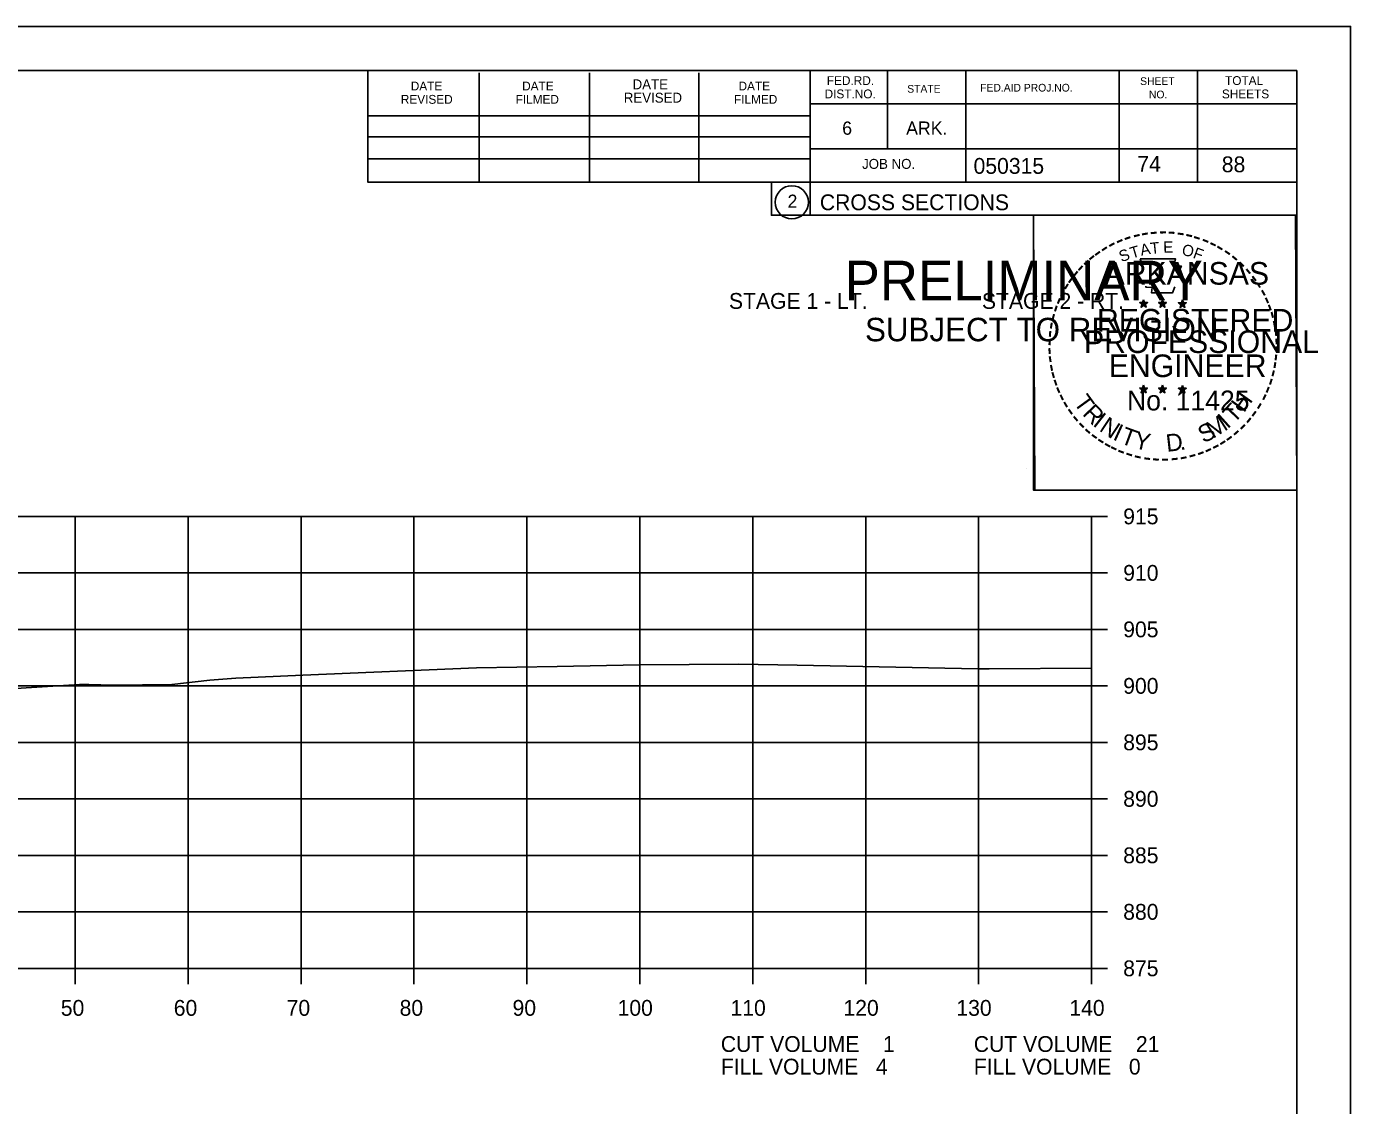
# Model space of a CAD drawing. Extents: x 1486524 to 1499135, y 326561 to 337924.
# Drawn here: x 1489028.6 to 1489145.8, y 333323.8 to 333419.3 of the extents above; entities that cross this region are included whole.
import ezdxf

# ---------------------------------------------------------------- set-up
doc = ezdxf.new("R2010")
doc.units = 0
for name, color, linetype in [('Default', 7, 'Continuous'), ('E_Const Align', 7, 'Continuous'), ('E_Const Align Station', 7, 'Continuous'), ('E_Ownership Information', 7, 'Continuous'), ('E_Property Line', 7, 'Continuous'), ('E_Quarter Calls', 7, 'Continuous'), ('E_Section Line', 7, 'Continuous'), ('E_Station Offset', 7, 'Continuous'), ('E_Tract Number', 7, 'Continuous'), ('S_SIXTEEN_SECTION', 7, 'Continuous')]:
    doc.layers.add(name, color=color, linetype=linetype)

msp = doc.modelspace()

# ---------------------------------------------------------------- linework, layer by layer
at = {"layer": 'E_Const Align'}
for p, q in [((1489122.89, 333335.96), (1489122.89, 333375.96)), ((1489124.29, 333375.96), (1489122.89, 333375.96)), ((1489124.29, 333370.96), (1489122.89, 333370.96)), ((1489124.29, 333365.96), (1489122.89, 333365.96)), ((1489124.29, 333360.96), (1489122.89, 333360.96)), ((1489124.29, 333355.96), (1489122.89, 333355.96)), ((1489124.29, 333350.96), (1489122.89, 333350.96)), ((1489124.29, 333345.96), (1489122.89, 333345.96)), ((1489124.29, 333340.96), (1489122.89, 333340.96)), ((1488842.89, 333335.96), (1489122.89, 333335.96)), ((1489032.89, 333334.56), (1489032.89, 333335.96)), ((1489042.89, 333334.56), (1489042.89, 333335.96)), ((1489052.89, 333334.56), (1489052.89, 333335.96)), ((1489062.89, 333334.56), (1489062.89, 333335.96)), ((1489072.89, 333334.56), (1489072.89, 333335.96)), ((1489082.89, 333334.56), (1489082.89, 333335.96)), ((1489092.89, 333334.56), (1489092.89, 333335.96)), ((1489102.89, 333334.56), (1489102.89, 333335.96)), ((1489112.89, 333334.56), (1489112.89, 333335.96)), ((1489122.89, 333334.56), (1489122.89, 333335.96)), ((1489124.29, 333335.96), (1489122.89, 333335.96))]:
    msp.add_line(p, q, dxfattribs=at)
at = {"layer": 'E_Ownership Information'}
for p, q in [((1488842.89, 333375.96), (1489122.89, 333375.96)), ((1489032.89, 333335.96), (1489032.89, 333375.96)), ((1489042.89, 333335.96), (1489042.89, 333375.96)), ((1489052.89, 333335.96), (1489052.89, 333375.96)), ((1489062.89, 333335.96), (1489062.89, 333375.96)), ((1489072.89, 333335.96), (1489072.89, 333375.96)), ((1489082.89, 333335.96), (1489082.89, 333375.96)), ((1489092.89, 333335.96), (1489092.89, 333375.96)), ((1489102.89, 333335.96), (1489102.89, 333375.96)), ((1489112.89, 333335.96), (1489112.89, 333375.96)), ((1489122.89, 333335.96), (1489122.89, 333375.96)), ((1488842.89, 333370.96), (1489122.89, 333370.96)), ((1488842.89, 333365.96), (1489122.89, 333365.96)), ((1488842.89, 333360.96), (1489122.89, 333360.96)), ((1488842.89, 333355.96), (1489122.89, 333355.96)), ((1488842.89, 333350.96), (1489122.89, 333350.96)), ((1488842.89, 333345.96), (1489122.89, 333345.96)), ((1488842.89, 333340.96), (1489122.89, 333340.96)), ((1488842.89, 333335.96), (1489122.89, 333335.96))]:
    msp.add_line(p, q, dxfattribs=at)
at = {"layer": 'E_Property Line'}
for p, q in [((1488824.89, 333415.42), (1489141.07, 333415.42)), ((1489058.81, 333405.54), (1489058.81, 333415.42)), ((1489068.67, 333405.54), (1489068.67, 333415.22)), ((1489078.43, 333405.54), (1489078.43, 333415.22)), ((1489088.11, 333405.54), (1489088.11, 333415.22)), ((1489097.97, 333415.42), (1489097.97, 333402.62)), ((1489104.81, 333415.42), (1489104.81, 333408.48)), ((1489111.75, 333415.42), (1489111.75, 333405.54)), ((1489125.33, 333415.42), (1489125.33, 333405.54)), ((1489132.27, 333415.42), (1489132.27, 333405.54)), ((1489141.07, 333209.96), (1489141.07, 333415.42)), ((1489141.07, 333412.48), (1489097.97, 333412.48)), ((1489141.07, 333412.5), (1489141.07, 333412.5)), ((1489058.81, 333411.4), (1489097.97, 333411.4)), ((1489058.81, 333409.54), (1489097.97, 333409.54)), ((1489058.81, 333405.54), (1489058.81, 333407.6)), ((1489058.81, 333407.6), (1489097.97, 333407.6)), ((1489141.07, 333408.48), (1489097.97, 333408.48)), ((1489100.93, 333408.48), (1489141.07, 333408.48)), ((1489141.07, 333405.54), (1489058.81, 333405.54)), ((1489097.97, 333402.62), (1489141.07, 333402.62))]:
    msp.add_line(p, q, dxfattribs=at)
msp.add_circle((1489096.35, 333403.76), 1.47, dxfattribs=at)
at = {"layer": 'E_Quarter Calls'}
for p, q in [((1488812.48, 333419.32), (1489145.82, 333419.32)), ((1489117.1, 333380.17), (1489117.1, 333380.17))]:
    msp.add_line(p, q, dxfattribs=at)
for points in [[(1488812.48, 333419.32), (1489145.82, 333419.32), (1489145.82, 333205.98), (1488812.48, 333205.98)], [(1489058.81, 333415.42), (1489058.81, 333405.54), (1489094.54, 333405.54), (1489094.54, 333402.62), (1489117.74, 333402.62), (1489117.74, 333378.29), (1489141.07, 333378.29), (1489141.07, 333209.96), (1488824.89, 333209.96), (1488824.89, 333415.42)], [(1489117.74, 333402.62), (1489140.94, 333402.62), (1489141.07, 333378.29), (1489117.86, 333378.29)]]:
    msp.add_lwpolyline(points, close=True, dxfattribs=at)
at = {"layer": 'E_Tract Number'}
msp.add_lwpolyline([(1489023.43, 333360.45), (1489029.49, 333360.85), (1489033.28, 333361.07), (1489034.1, 333361.07), (1489036.23, 333361.02), (1489041.45, 333361.07), (1489044.82, 333361.46), (1489047.12, 333361.63), (1489053.05, 333361.91), (1489068.42, 333362.56), (1489075.58, 333362.66), (1489082.86, 333362.82), (1489091.67, 333362.88), (1489096.82, 333362.79), (1489112.82, 333362.48), (1489113.55, 333362.48), (1489113.82, 333362.48), (1489122.89, 333362.52)], dxfattribs=at)
at = {"layer": 'S_SIXTEEN_SECTION'}
for p, q in [((1489127.15, 333394.88), (1489127.5, 333394.77)), ((1489127.15, 333394.88), (1489127.4, 333394.84)), ((1489127.15, 333394.88), (1489127.39, 333394.76)), ((1489127.28, 333394.47), (1489127.5, 333394.77)), ((1489127.28, 333394.47), (1489127.41, 333394.72)), ((1489127.28, 333394.47), (1489127.5, 333394.69)), ((1489127.5, 333395.13), (1489127.46, 333394.88)), ((1489127.5, 333394.77), (1489127.5, 333395.13)), ((1489127.5, 333395.13), (1489127.55, 333394.88)), ((1489127.85, 333394.88), (1489127.5, 333394.77)), ((1489127.71, 333394.47), (1489127.5, 333394.77)), ((1489127.71, 333394.47), (1489127.5, 333394.69)), ((1489127.85, 333394.88), (1489127.56, 333394.83)), ((1489127.71, 333394.47), (1489127.58, 333394.76)), ((1489127.85, 333394.88), (1489127.64, 333394.78)), ((1489128.82, 333394.88), (1489129.17, 333394.77)), ((1489128.82, 333394.88), (1489129.07, 333394.84)), ((1489128.82, 333394.88), (1489129.06, 333394.76)), ((1489128.95, 333394.47), (1489129.17, 333394.77)), ((1489128.95, 333394.47), (1489129.08, 333394.72)), ((1489128.95, 333394.47), (1489129.17, 333394.69)), ((1489129.17, 333395.13), (1489129.13, 333394.88)), ((1489129.17, 333394.77), (1489129.17, 333395.13)), ((1489129.17, 333395.13), (1489129.22, 333394.88)), ((1489129.52, 333394.88), (1489129.17, 333394.77)), ((1489129.38, 333394.47), (1489129.17, 333394.77)), ((1489129.38, 333394.47), (1489129.17, 333394.69)), ((1489129.52, 333394.88), (1489129.23, 333394.83)), ((1489129.38, 333394.47), (1489129.25, 333394.76)), ((1489129.52, 333394.88), (1489129.31, 333394.78)), ((1489130.58, 333394.87), (1489130.93, 333394.76)), ((1489130.58, 333394.87), (1489130.84, 333394.82)), ((1489130.58, 333394.87), (1489130.82, 333394.75)), ((1489130.72, 333394.46), (1489130.93, 333394.76)), ((1489130.72, 333394.46), (1489130.84, 333394.7)), ((1489130.72, 333394.46), (1489130.93, 333394.68)), ((1489130.93, 333395.12), (1489130.89, 333394.87)), ((1489130.93, 333394.76), (1489130.93, 333395.12)), ((1489130.93, 333395.12), (1489130.98, 333394.87)), ((1489131.28, 333394.87), (1489130.93, 333394.76)), ((1489131.15, 333394.46), (1489130.93, 333394.76)), ((1489131.15, 333394.46), (1489130.93, 333394.67)), ((1489131.28, 333394.87), (1489130.99, 333394.82)), ((1489131.15, 333394.46), (1489131.01, 333394.75)), ((1489131.28, 333394.87), (1489131.08, 333394.77)), ((1489127.15, 333387.31), (1489127.5, 333387.2)), ((1489127.15, 333387.31), (1489127.4, 333387.26)), ((1489127.15, 333387.31), (1489127.38, 333387.19)), ((1489127.28, 333386.9), (1489127.5, 333387.2)), ((1489127.28, 333386.9), (1489127.41, 333387.14)), ((1489127.28, 333386.9), (1489127.49, 333387.12)), ((1489127.5, 333387.56), (1489127.45, 333387.31)), ((1489127.71, 333386.9), (1489127.49, 333387.11)), ((1489127.5, 333387.2), (1489127.5, 333387.56)), ((1489127.5, 333387.56), (1489127.54, 333387.31)), ((1489127.84, 333387.31), (1489127.5, 333387.2)), ((1489127.71, 333386.9), (1489127.5, 333387.2)), ((1489127.84, 333387.31), (1489127.56, 333387.26)), ((1489127.71, 333386.9), (1489127.57, 333387.19)), ((1489127.84, 333387.31), (1489127.64, 333387.21)), ((1489128.82, 333387.31), (1489129.16, 333387.2)), ((1489128.82, 333387.31), (1489129.07, 333387.26)), ((1489128.82, 333387.31), (1489129.05, 333387.19)), ((1489128.95, 333386.9), (1489129.16, 333387.2)), ((1489128.95, 333386.9), (1489129.07, 333387.14)), ((1489128.95, 333386.9), (1489129.16, 333387.12)), ((1489129.16, 333387.56), (1489129.12, 333387.31)), ((1489129.16, 333387.2), (1489129.16, 333387.56)), ((1489129.16, 333387.56), (1489129.21, 333387.31)), ((1489129.51, 333387.31), (1489129.16, 333387.2)), ((1489129.38, 333386.9), (1489129.16, 333387.2)), ((1489129.38, 333386.9), (1489129.16, 333387.11)), ((1489129.51, 333387.31), (1489129.23, 333387.26)), ((1489129.38, 333386.9), (1489129.24, 333387.19)), ((1489129.51, 333387.31), (1489129.31, 333387.21)), ((1489130.58, 333387.3), (1489130.93, 333387.19)), ((1489130.58, 333387.3), (1489130.84, 333387.25)), ((1489130.58, 333387.3), (1489130.82, 333387.18)), ((1489130.72, 333386.89), (1489130.93, 333387.19)), ((1489130.72, 333386.89), (1489130.84, 333387.13)), ((1489130.72, 333386.89), (1489130.93, 333387.11)), ((1489130.93, 333387.55), (1489130.89, 333387.3)), ((1489130.93, 333387.19), (1489130.93, 333387.55)), ((1489130.93, 333387.55), (1489130.98, 333387.3)), ((1489131.28, 333387.3), (1489130.93, 333387.19)), ((1489131.14, 333386.89), (1489130.93, 333387.19)), ((1489131.14, 333386.89), (1489130.93, 333387.1)), ((1489131.28, 333387.3), (1489130.99, 333387.25)), ((1489131.14, 333386.89), (1489131.01, 333387.18)), ((1489131.28, 333387.3), (1489131.07, 333387.2))]:
    msp.add_line(p, q, dxfattribs=at)
for points in [[(1489127.19, 333398.76), (1489127.46, 333397.93)], [(1489130.7, 333397.84), (1489130.84, 333398.12), (1489130.16, 333398.1), (1489130.31, 333398.76), (1489127.19, 333398.76)], [(1489127.68, 333396.34), (1489127.68, 333396.25), (1489128.25, 333396.23), (1489128.19, 333395.76), (1489130.06, 333395.76), (1489130.26, 333396.29)], [(1489127.5, 333395.13), (1489127.71, 333394.47), (1489127.15, 333394.88), (1489127.85, 333394.88), (1489127.28, 333394.47), (1489127.5, 333395.13)], [(1489129.17, 333395.13), (1489129.38, 333394.47), (1489128.82, 333394.88), (1489129.52, 333394.88), (1489128.95, 333394.47), (1489129.17, 333395.13)], [(1489130.93, 333395.12), (1489131.15, 333394.46), (1489130.58, 333394.87), (1489131.28, 333394.87), (1489130.72, 333394.46), (1489130.93, 333395.12)], [(1489127.5, 333387.56), (1489127.71, 333386.9), (1489127.15, 333387.31), (1489127.84, 333387.31), (1489127.28, 333386.9), (1489127.5, 333387.56)], [(1489129.16, 333387.56), (1489129.38, 333386.9), (1489128.82, 333387.31), (1489129.51, 333387.31), (1489128.95, 333386.9), (1489129.16, 333387.56)], [(1489130.93, 333387.55), (1489131.14, 333386.89), (1489130.58, 333387.3), (1489131.28, 333387.3), (1489130.72, 333386.89), (1489130.93, 333387.55)]]:
    msp.add_lwpolyline(points, dxfattribs=at)
for centre, radius in [((1489127.5, 333394.77), 0.172), ((1489127.5, 333394.77), 0.145), ((1489127.5, 333394.77), 0.116), ((1489127.5, 333394.77), 0.0991), ((1489127.5, 333394.77), 0.0747), ((1489127.5, 333394.77), 0.0495), ((1489127.5, 333394.77), 0.0296), ((1489129.17, 333394.77), 0.172), ((1489129.17, 333394.77), 0.145), ((1489129.17, 333394.77), 0.116), ((1489129.17, 333394.77), 0.0991), ((1489129.17, 333394.77), 0.0747), ((1489129.17, 333394.77), 0.0495), ((1489129.17, 333394.77), 0.0296), ((1489130.93, 333394.76), 0.172), ((1489130.93, 333394.76), 0.145), ((1489130.93, 333394.76), 0.116), ((1489130.93, 333394.76), 0.0991), ((1489130.93, 333394.76), 0.0747), ((1489130.93, 333394.76), 0.0495), ((1489130.93, 333394.76), 0.0296), ((1489127.49, 333387.2), 0.172), ((1489127.49, 333387.2), 0.145), ((1489127.49, 333387.2), 0.116), ((1489127.49, 333387.2), 0.0991), ((1489127.49, 333387.2), 0.0747), ((1489127.49, 333387.2), 0.0495), ((1489127.49, 333387.2), 0.0296), ((1489129.16, 333387.2), 0.172), ((1489129.16, 333387.2), 0.145), ((1489129.16, 333387.2), 0.116), ((1489129.16, 333387.2), 0.0991), ((1489129.16, 333387.2), 0.0747), ((1489129.16, 333387.2), 0.0495), ((1489129.16, 333387.2), 0.0296), ((1489130.93, 333387.19), 0.172), ((1489130.93, 333387.19), 0.145), ((1489130.93, 333387.19), 0.116), ((1489130.93, 333387.19), 0.0991), ((1489130.93, 333387.19), 0.0747), ((1489130.93, 333387.19), 0.0495), ((1489130.93, 333387.19), 0.0296)]:
    msp.add_circle(centre, radius, dxfattribs=at)

# ---------------------------------------------------------------- texts
at = {"layer": 'Default'}
for s, p in [('STAGE 1 - LT.', (1489090.78, 333394.33)), ('STAGE 2 - RT.', (1489113.18, 333394.33))]:
    msp.add_text(s, height=1.4, dxfattribs=at).set_placement(p)
at = {"layer": 'E_Const Align Station'}
for s, p in [('915', (1489125.69, 333375.26)), ('910', (1489125.69, 333370.26)), ('905', (1489125.69, 333365.26)), ('900', (1489125.69, 333360.26)), ('895', (1489125.69, 333355.26)), ('890', (1489125.69, 333350.26)), ('885', (1489125.69, 333345.26)), ('880', (1489125.69, 333340.26)), ('875', (1489125.69, 333335.26)), ('50', (1489031.62, 333331.76)), ('60', (1489041.62, 333331.76)), ('70', (1489051.62, 333331.76)), ('80', (1489061.62, 333331.76)), ('90', (1489071.62, 333331.76)), ('100', (1489080.92, 333331.76)), ('110', (1489090.92, 333331.76)), ('120', (1489100.92, 333331.76)), ('130', (1489110.92, 333331.76)), ('140', (1489120.92, 333331.76)), ('CUT VOLUME    1', (1489090.06, 333328.56)), ('CUT VOLUME    21', (1489112.46, 333328.56)), ('FILL VOLUME   4', (1489090.06, 333326.56)), ('FILL VOLUME   0', (1489112.46, 333326.56))]:
    msp.add_text(s, height=1.4, dxfattribs=at).set_placement(p)
at = {"layer": 'E_Property Line'}
for s, height, p in [('DATE', 0.879, (1489082.25, 333413.76)), ('FED.RD.', 0.782, (1489099.45, 333414.14)), ('SHEET', 0.684, (1489127.19, 333414.14)), ('TOTAL', 0.782, (1489134.71, 333414.14)), ('DATE', 0.782, (1489062.61, 333413.66)), ('DATE', 0.782, (1489072.47, 333413.66)), ('REVISED', 0.879, (1489081.47, 333412.58)), ('DATE', 0.782, (1489091.63, 333413.66)), ('DIST.NO.', 0.782, (1489099.25, 333412.96)), ('STATE', 0.684, (1489106.57, 333413.46)), ('FED.AID PROJ.NO.', 0.684, (1489113.03, 333413.56)), ('NO.', 0.684, (1489127.97, 333412.96)), ('SHEETS', 0.782, (1489134.43, 333412.96)), ('REVISED', 0.782, (1489061.73, 333412.48)), ('FILMED', 0.782, (1489071.89, 333412.48)), ('FILMED', 0.782, (1489091.23, 333412.48)), ('6', 1.17, (1489100.81, 333409.74)), ('ARK.', 1.172, (1489106.47, 333409.74)), ('JOB NO.', 0.879, (1489102.57, 333406.72)), ('050315', 1.4, (1489112.44, 333406.28)), ('2', 1.17, (1489095.97, 333403.27)), ('CROSS SECTIONS', 1.4, (1489098.83, 333403.06))]:
    msp.add_text(s, height=height, rotation=360, dxfattribs=at).set_placement(p)
at = {"layer": 'E_Section Line'}
for s, height, p in [('PRELIMINARY', 3.5, (1489101.02, 333395.09)), ('DWB', 0.01, (1489101.76, 333396.94)), ('SUBJECT TO REVISION', 2.0751, (1489102.83, 333391.46))]:
    msp.add_text(s, height=height, rotation=360, dxfattribs=at).set_placement(p)
at = {"layer": 'E_Station Offset'}
for s, p in [('74', (1489126.94, 333406.46)), ('88', (1489134.42, 333406.42))]:
    msp.add_text(s, height=1.4, dxfattribs=at).set_placement(p)
at = {"layer": 'S_SIXTEEN_SECTION'}
for s, height, rotation, p in [('-', 1.6, 19.1761, (1489125.94, 333399.89)), ('-', 1.6, 13.6301, (1489126.69, 333400.13)), ('-', 1.6, 10.2193, (1489127.37, 333400.29)), ('-', 1.6, 5.8968, (1489128.1, 333400.4)), ('-', 1.6, 0.1862, (1489128.87, 333400.47)), ('-', 1.6, 357.743, (1489129.59, 333400.46)), ('-', 1.6, 352.1617, (1489130.34, 333400.4)), ('-', 1.6, 347.2049, (1489131.05, 333400.29)), ('-', 1.6, 342.3362, (1489131.69, 333400.13)), ('-', 1.6, 337.8551, (1489132.42, 333399.91)), ('-', 1.6, 36.2317, (1489123.5, 333398.53)), ('-', 1.6, 34.0636, (1489124.08, 333398.93)), ('-', 1.6, 28.7918, (1489124.67, 333399.3)), ('-', 1.6, 24.3072, (1489125.31, 333399.62)), ('S', 1, 21.594, (1489125.55, 333398.44)), ('T', 1, 16.4036, (1489126.46, 333398.77)), ('A', 1, 11.2132, (1489127.29, 333399.02)), ('T', 1, 6.0228, (1489128.14, 333399.18)), ('E', 1, 0.8323, (1489129.24, 333399.29)), ('O', 1, 350.4515, (1489130.84, 333399.08)), ('F', 1, 340.0707, (1489131.8, 333398.86)), ('-', 1.6, 334.1211, (1489133.06, 333399.64)), ('-', 1.6, 329.6409, (1489133.63, 333399.36)), ('-', 1.6, 325.8627, (1489134.28, 333398.99)), ('-', 1.6, 48.423, (1489122.14, 333397.26)), ('-', 1.6, 42.9622, (1489122.59, 333397.74)), ('-', 1.6, 38.9507, (1489123.02, 333398.16)), ('ARKANSAS', 2, 360, (1489124.04, 333396.47)), ('-', 1.6, 320.5297, (1489134.89, 333398.57)), ('-', 1.6, 315.5786, (1489135.49, 333398.08)), ('-', 1.6, 54.2325, (1489121.32, 333396.21)), ('-', 1.6, 50.6142, (1489121.74, 333396.78)), ('-', 1.6, 309.8797, (1489136.06, 333397.53)), ('-', 1.6, 306.6522, (1489136.58, 333396.93)), ('-', 1.6, 62.8713, (1489120.69, 333395.07)), ('-', 1.6, 58.0706, (1489121, 333395.68)), ('-', 1.4, 303.6753, (1489137.07, 333396.36)), ('-', 1.6, 299.6684, (1489137.39, 333395.75)), ('-', 1.6, 67.7743, (1489120.43, 333394.46)), ('DWB', 0.01, 360, (1489127.49, 333394.76)), ('DWB', 0.01, 360, (1489129.16, 333394.76)), ('DWB', 0.01, 360, (1489130.92, 333394.75)), ('-', 1.6, 294.6628, (1489137.71, 333395.14)), ('-', 1.6, 290.5728, (1489137.97, 333394.56)), ('-', 1.6, 75.461, (1489120.01, 333393.11)), ('-', 1.6, 72.3945, (1489120.21, 333393.83)), ('REGISTERED', 2, 360, (1489123.37, 333392.32)), ('-', 1.6, 285.1233, (1489138.2, 333393.98)), ('-', 1.6, 85.1863, (1489119.8, 333391.71)), ('-', 1.6, 81.2013, (1489119.88, 333392.4)), ('PROFESSIONAL', 2, 360, (1489122.22, 333390.42)), ('-', 1.6, 280.5493, (1489138.4, 333393.24)), ('-', 1.6, 276.5962, (1489138.56, 333392.47)), ('-', 1.6, 89.0622, (1489119.78, 333391.01)), ('-', 1.6, 274.3301, (1489138.62, 333391.75)), ('-', 1.6, 94.1959, (1489119.81, 333390.28)), ('-', 1.6, 98.9479, (1489119.89, 333389.62)), ('ENGINEER', 2, 360, (1489124.41, 333388.29)), ('-', 1.6, 263.5172, (1489138.64, 333390.45)), ('-', 1.6, 269.9407, (1489138.66, 333391.12)), ('-', 1.6, 101.7149, (1489120.02, 333388.88)), ('-', 1.6, 255.7626, (1489138.46, 333389.12)), ('-', 1.6, 260.9953, (1489138.57, 333389.8)), ('-', 1.6, 105.4578, (1489120.18, 333388.29)), ('-', 1.6, 109.0874, (1489120.4, 333387.66)), ('-', 1.6, 252.8681, (1489138.28, 333388.4)), ('-', 1.6, 114.0643, (1489120.65, 333387.06)), ('-', 1.6, 115.7289, (1489120.96, 333386.44)), ('T', 1.54, 306.0406, (1489121.25, 333386.03)), ('No. 11425', 1.757, 360, (1489126.03, 333385.34)), ('DWB', 0.01, 360, (1489127.48, 333387.19)), ('DWB', 0.01, 360, (1489129.15, 333387.19)), ('DWB', 0.01, 360, (1489130.92, 333387.18)), ('H', 1.54, 54.6088, (1489136.38, 333385.07)), ('-', 1.6, 244.6197, (1489137.79, 333387.1)), ('-', 1.6, 247.8887, (1489138.05, 333387.73)), ('-', 1.6, 120.4471, (1489121.31, 333385.86)), ('-', 1.6, 125.8934, (1489121.72, 333385.3)), ('R', 1.54, 314.005, (1489122.02, 333384.99)), ('T', 1.54, 46.6444, (1489135.49, 333384.13)), ('-', 1.6, 233.8452, (1489136.99, 333385.7)), ('-', 1.6, 239.0712, (1489137.4, 333386.35)), ('-', 1.6, 130.7181, (1489122.18, 333384.74)), ('-', 1.6, 134.2238, (1489122.7, 333384.2)), ('I', 1.54, 321.9694, (1489122.92, 333384.05)), ('N', 1.54, 326.5002, (1489123.49, 333383.58)), ('I', 1.54, 335.3603, (1489124.69, 333382.8)), ('S', 1.54, 26.9312, (1489132.8, 333382.4)), ('M', 1.54, 32.6563, (1489133.64, 333382.8)), ('I', 1.54, 42.1136, (1489134.92, 333383.65)), ('-', 1.6, 225.7653, (1489136.09, 333384.57)), ('-', 1.6, 231.2538, (1489136.56, 333385.13)), ('-', 1.6, 138.9338, (1489123.22, 333383.73)), ('-', 1.6, 144.6463, (1489123.78, 333383.33)), ('T', 1.54, 339.8912, (1489125.35, 333382.47)), ('Y', 1.54, 347.8556, (1489126.57, 333382.02)), ('D', 1.54, 6.3969, (1489129.56, 333381.67)), ('-', 1.6, 215.7363, (1489135.01, 333383.58)), ('-', 1.6, 221.0851, (1489135.56, 333384.06)), ('-', 1.6, 148.0898, (1489124.34, 333382.96)), ('-', 1.6, 151.5704, (1489124.92, 333382.63)), ('-', 1.6, 154.6002, (1489125.44, 333382.39)), ('-', 1.6, 158.5612, (1489126.06, 333382.13)), ('.', 1.54, 13.7642, (1489130.75, 333381.79)), ('-', 1.6, 204.2516, (1489133.3, 333382.53)), ('-', 1.6, 207.3568, (1489133.92, 333382.85)), ('-', 1.6, 212.2491, (1489134.48, 333383.2)), ('-', 1.6, 162.7983, (1489126.75, 333381.92)), ('-', 1.6, 167.5555, (1489127.46, 333381.75)), ('-', 1.6, 173.1155, (1489128.24, 333381.64)), ('-', 1.6, 176.5183, (1489128.98, 333381.59)), ('-', 1.6, 181.5918, (1489129.73, 333381.61)), ('-', 1.6, 185.8167, (1489130.54, 333381.69)), ('-', 1.6, 191.2858, (1489131.27, 333381.82)), ('-', 1.6, 195.4743, (1489132, 333382.02)), ('-', 1.6, 200.7184, (1489132.68, 333382.26))]:
    msp.add_text(s, height=height, rotation=rotation, dxfattribs=at).set_placement(p)

doc.saveas('drawing.dxf')
